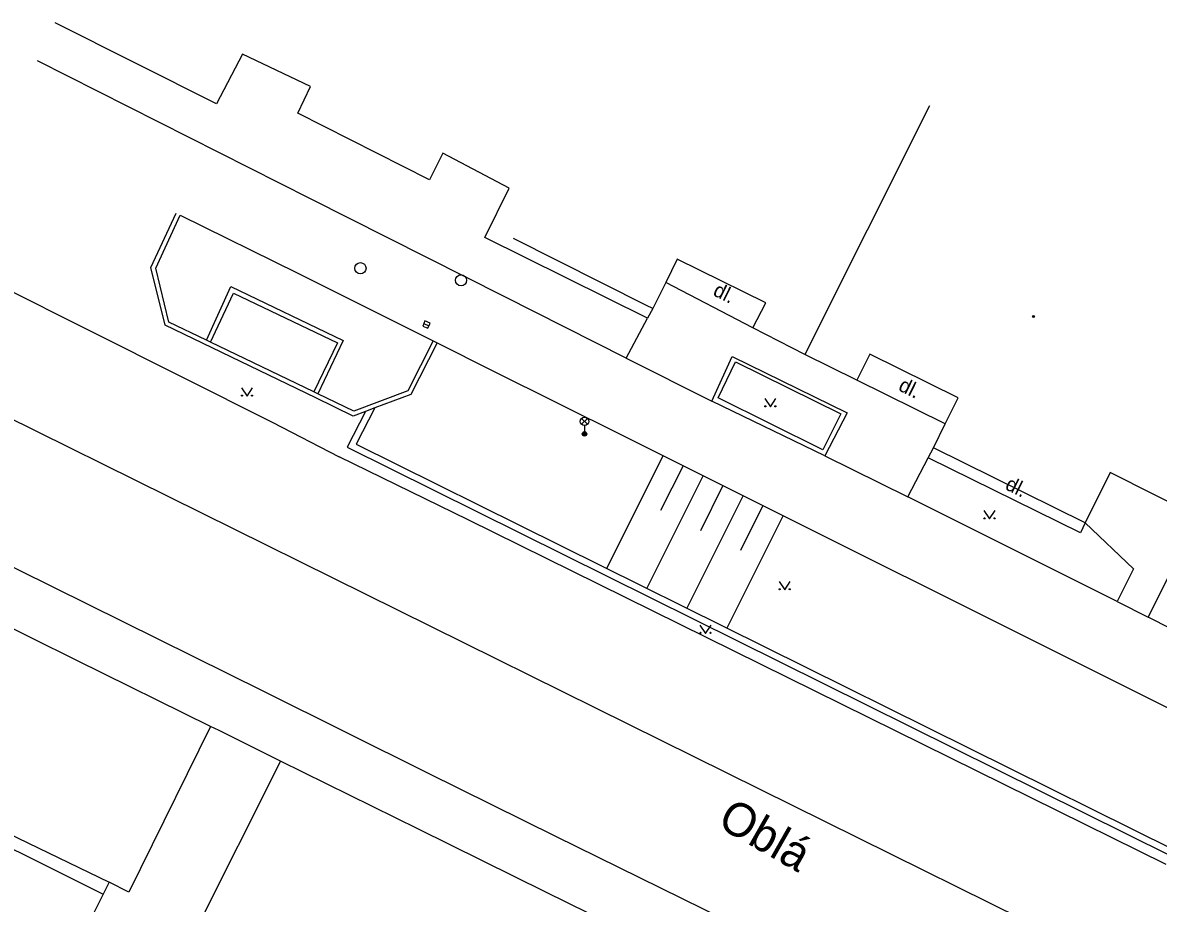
# Model space of a CAD drawing. Extents: x -602419 to -601554, y -1162937 to -1162362.
# Drawn here: x -602178.2 to -602127.5, y -1162437.8 to -1162398.4 of the extents above; entities that cross this region are included whole.
import ezdxf

# ---------------------------------------------------------------- set-up
doc = ezdxf.new("R2010")
doc.units = 0
doc.layers.add('Podklad', color=7, linetype='Continuous')

msp = doc.modelspace()

# ---------------------------------------------------------------- linework, layer by layer
at = {"layer": 'Podklad'}
for p, q in [((-602160.3147, -1162411.8903), (-602160.0853, -1162411.9897)), ((-602153.2625, -1162416.4), (-602152.9975, -1162416.135)), ((-602153.2625, -1162416.135), (-602152.9975, -1162416.4)), ((-602153.13, -1162416.455), (-602153.13, -1162416.83))]:
    msp.add_line(p, q, dxfattribs=at)
for points in [[(-602150.31, -1162411.6599), (-602157.58, -1162408.05), (-602156.5, -1162405.84), (-602159.46, -1162404.28), (-602160.06, -1162405.46), (-602165.95, -1162402.48), (-602165.38, -1162401.3), (-602168.43, -1162399.84), (-602169.58, -1162402.07), (-602176.8, -1162398.44)], [(-602151.27, -1162413.44), (-602156.7199, -1162410.68), (-602165.38, -1162406.31), (-602177.59, -1162400.14)], [(-602198.54, -1162400.86), (-602187.49, -1162406.08), (-602167.1, -1162416.31), (-602164.1, -1162417.86)], [(-602137.71, -1162402.1599), (-602143.28, -1162413.28)], [(-602204.06, -1162403.64), (-602127.68, -1162441.44)], [(-602162.92, -1162415.82), (-602163.4699, -1162416.03), (-602165.14, -1162415.2199), (-602171.88, -1162411.9699), (-602172.52, -1162409.39), (-602171.39, -1162406.95)], [(-602172.3, -1162409.4099), (-602171.21, -1162407.04)], [(-602171.21, -1162407.04), (-602165.95, -1162409.64), (-602159.89, -1162412.67)], [(-602150.36, -1162411.08), (-602156.3, -1162408.09)], [(-602148.98, -1162409.02), (-602149.5, -1162410.06)], [(-602145.03, -1162410.96), (-602148.98, -1162409.02)], [(-602171.71, -1162411.83), (-602172.3, -1162409.4099)], [(-602170.03, -1162412.64), (-602168.94, -1162410.24), (-602163.92, -1162412.65), (-602165.05, -1162415.04)], [(-602149.5, -1162410.06), (-602150.07, -1162411.2199)], [(-602145.6, -1162412.08), (-602149.5, -1162410.06)], [(-602169.85, -1162412.73), (-602168.83, -1162410.53), (-602164.18, -1162412.75), (-602165.23, -1162414.95)], [(-602202.73, -1162410.9099), (-602189.44, -1162417.46), (-602167.49, -1162428.34), (-602160.15, -1162431.98), (-602154.43, -1162434.82), (-602132.77, -1162445.48), (-602129.7, -1162447.06), (-602126.44, -1162448.64)], [(-602150.07, -1162411.2199), (-602150.36, -1162411.08)], [(-602150.07, -1162411.2199), (-602150.31, -1162411.6599)], [(-602145.6, -1162412.08), (-602145.03, -1162410.96)], [(-602170.03, -1162412.64), (-602171.71, -1162411.83)], [(-602151.27, -1162413.44), (-602150.31, -1162411.6599)], [(-602143.28, -1162413.28), (-602145.6, -1162412.08)], [(-602169.85, -1162412.73), (-602170.03, -1162412.64)], [(-602165.23, -1162414.95), (-602169.85, -1162412.73)], [(-602159.7199, -1162412.76), (-602160.89, -1162415.07), (-602162.51, -1162415.67)], [(-602159.89, -1162412.67), (-602161.03, -1162414.9099)], [(-602159.89, -1162412.67), (-602159.7199, -1162412.76)], [(-602159.7199, -1162412.76), (-602157.26, -1162413.99), (-602151.36, -1162416.93), (-602126.27, -1162429.4699), (-602124.32, -1162430.46)], [(-602147.44, -1162415.36), (-602146.53, -1162413.36), (-602141.38, -1162415.88), (-602142.38, -1162417.81)], [(-602140.95, -1162414.43), (-602143.28, -1162413.28)], [(-602140.37, -1162413.26), (-602140.95, -1162414.43)], [(-602136.42, -1162415.21), (-602140.37, -1162413.26)], [(-602151.27, -1162413.44), (-602147.44, -1162415.36)], [(-602147.1599, -1162415.2199), (-602146.38, -1162413.61), (-602141.67, -1162415.93), (-602142.4699, -1162417.54), (-602147.1599, -1162415.2199)], [(-602168.4699, -1162414.765), (-602168.2199, -1162415.14), (-602167.9699, -1162414.765)], [(-602161.03, -1162414.9099), (-602163.45, -1162415.81)], [(-602137, -1162416.38), (-602140.95, -1162414.43)], [(-602165.05, -1162415.04), (-602165.23, -1162414.95)], [(-602163.45, -1162415.81), (-602165.05, -1162415.04)], [(-602142.38, -1162417.81), (-602147.44, -1162415.36)], [(-602145.07, -1162415.245), (-602144.82, -1162415.62), (-602144.57, -1162415.245)], [(-602137, -1162416.38), (-602136.42, -1162415.21)], [(-602162.92, -1162415.82), (-602163.74, -1162417.42), (-602126.94, -1162435.69)], [(-602162.51, -1162415.67), (-602163.34, -1162417.29), (-602126.8, -1162435.42)], [(-602162.51, -1162415.67), (-602162.92, -1162415.82)], [(-602137.53, -1162417.45), (-602137, -1162416.38)], [(-602137.76, -1162417.9), (-602137.53, -1162417.45)], [(-602130.75, -1162420.8), (-602137.53, -1162417.45)], [(-602127.13, -1162436.09), (-602152.5, -1162423.55), (-602158.33, -1162420.67), (-602164.1, -1162417.86)], [(-602149.62, -1162417.8), (-602152.14, -1162422.85)], [(-602142.38, -1162417.81), (-602138.68, -1162419.65)], [(-602138.68, -1162419.65), (-602137.76, -1162417.9)], [(-602130.75, -1162420.8), (-602130.96, -1162421.26), (-602137.76, -1162417.9)], [(-602148.7199, -1162418.25), (-602149.73, -1162420.26)], [(-602147.83, -1162418.69), (-602150.35, -1162423.73)], [(-602129.63, -1162418.56), (-602130.75, -1162420.8)], [(-602125.69, -1162420.53), (-602129.63, -1162418.56)], [(-602146.94, -1162419.14), (-602147.94, -1162421.1599)], [(-602146.04, -1162419.59), (-602148.56, -1162424.62)], [(-602129.31, -1162424.33), (-602138.68, -1162419.65)], [(-602144.25, -1162420.48), (-602146.77, -1162425.51)], [(-602145.15, -1162420.03), (-602146.15, -1162422.05)], [(-602135.27, -1162420.255), (-602135.02, -1162420.63), (-602134.77, -1162420.255)], [(-602130.75, -1162420.8), (-602128.58, -1162422.87), (-602129.31, -1162424.33)], [(-602169.86, -1162429.9099), (-602175.83, -1162426.96), (-602186.05, -1162421.89)], [(-602126.5, -1162422.14), (-602127.93, -1162425.03)], [(-602120.55, -1162422.9699), (-602122.85, -1162427.6), (-602127.93, -1162425.03)], [(-602144.43, -1162423.425), (-602144.18, -1162423.8), (-602143.93, -1162423.425)], [(-602129.31, -1162424.33), (-602127.93, -1162425.03)], [(-602147.9699, -1162425.375), (-602147.7199, -1162425.75), (-602147.4699, -1162425.375)], [(-602189.86, -1162429.39), (-602182.13, -1162433.13), (-602174.39, -1162436.88)], [(-602169.86, -1162429.9099), (-602173.5, -1162437.32)], [(-602166.7199, -1162431.4699), (-602169.47, -1162430.1), (-602169.86, -1162429.9099)], [(-602166.7199, -1162431.4699), (-602170.53, -1162439.04)], [(-602160.56, -1162434.51), (-602166.7199, -1162431.4699)], [(-602182.35, -1162433.58), (-602174.65, -1162437.4099)], [(-602154.86, -1162437.32), (-602160.56, -1162434.51)], [(-602174.39, -1162436.88), (-602174.65, -1162437.4099)], [(-602173.5, -1162437.32), (-602174.39, -1162436.88)], [(-602174.65, -1162437.4099), (-602175.23, -1162438.57)], [(-602150.11, -1162439.6599), (-602154.86, -1162437.32)]]:
    msp.add_lwpolyline(points, dxfattribs=at)
msp.add_lwpolyline([(-602160.3644, -1162412.0049), (-602160.1351, -1162412.1044), (-602160.0356, -1162411.8751), (-602160.2649, -1162411.7756)], close=True, dxfattribs=at)
for centre, radius in [((-602163.15, -1162409.42), 0.25), ((-602158.65, -1162409.96), 0.25), ((-602133.06, -1162411.58), 0.045), ((-602133.06, -1162411.58), 0.0199), ((-602168.445, -1162415.1149), 0.025), ((-602167.9953, -1162415.1149), 0.025), ((-602145.0451, -1162415.5949), 0.025), ((-602144.5954, -1162415.5949), 0.025), ((-602153.13, -1162416.2675), 0.1875), ((-602153.13, -1162416.83), 0.1), ((-602153.13, -1162416.83), 0.0723), ((-602153.13, -1162416.83), 0.0438), ((-602135.2451, -1162420.6049), 0.025), ((-602134.7954, -1162420.6049), 0.025), ((-602144.4051, -1162423.7749), 0.025), ((-602143.9554, -1162423.7749), 0.025), ((-602147.945, -1162425.7249), 0.025), ((-602147.4953, -1162425.7249), 0.025)]:
    msp.add_circle(centre, radius, dxfattribs=at)

# ---------------------------------------------------------------- texts
for s, height, rotation, p in [('dl.', 0.65, 333.67, (-602147.43, -1162410.61)), ('dl.', 0.65, 333.67, (-602139.14, -1162414.86)), ('dl.', 0.65, 333.67, (-602134.37, -1162419.28)), ('Oblá', 1.5, 330.4, (-602147.25, -1162434.36))]:
    msp.add_text(s, height=height, rotation=rotation, dxfattribs=at).set_placement(p)

doc.saveas('drawing.dxf')
